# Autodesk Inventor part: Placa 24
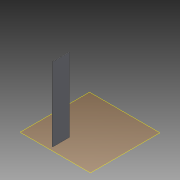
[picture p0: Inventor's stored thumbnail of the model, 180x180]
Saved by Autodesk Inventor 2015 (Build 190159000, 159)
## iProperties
Created: 2015-04
Part Number: Placa 24
Material: Generic
Document SubType Name: Modeling
Designer: suporte
Density: 1 g/cm^3
Appearance: Default
Author: suporte
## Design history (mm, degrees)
workplane "Work Plane1"
sketch "Sketch1"
  geometry: L1 (-175, -887.5)-(-187.5, -887.5); L2 (-187.5, -887.5)-(-187.5, -412.5); L3 (-187.5, -412.5)-(-175, -412.5); L4 (-175, -412.5)-(-175, -887.5); 1 further point
  constraints: 8 end point, 2 parallel, 1 horizontal, 1 perpendicular, 2 other
extrude "Extrusion1" new body sketch "Sketch1" distance "d0" = 2100; taper "d1" = 0 deg
body "Solid1"
